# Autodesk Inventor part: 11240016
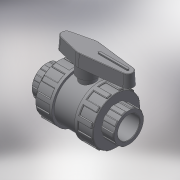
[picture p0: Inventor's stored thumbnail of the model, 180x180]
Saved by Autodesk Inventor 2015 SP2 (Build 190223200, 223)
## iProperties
Created: 2017-11
Part Number: 11240016
Material: Generic
Description: PLASSON BI STOP VALVE CEM PVC 16
Document SubType Name: Modeling
Designer: KIM
Density: 1 g/cm^3
Appearance: Default
Author: KIM
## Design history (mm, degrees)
derived "112400 - 112700.ipt"
feature "Solid1::112400 - 112700.ipt"
tag "TaggingFeature1"
body "Solid1"
other parameters: "d0" = 71, "d1" = 16, "d2" = 45, "d3" = 14, "d4" = 12.8, "d5" = 9.8, "d7" = 22.4, "d8" = 40.5, "d13" = 0.48, "d23" = 14, "d24" = 43.2, "d25" = 0.32, "d26" = 0.48, "d27" = 6.75, "d28" = 3.375, "d29" = 10.5, "d30" = 0, "d35" = 0.48, "d39" = 22.5, "d45" = 360 deg, "d47" = 0.32, "d50" = 24.75, "d51" = 13.5, "d53" = 0, "d55" = 3.2, "d56" = 1.6, "d57" = 9.8, "d58" = 0, "d59" = 0.48, "d61" = 360 deg, "d63" = 18, "d64" = 45, "d66" = 65, "d68" = 9, "d69" = 19.5, "d70" = 11.25, "d71" = 3 deg, "d73" = 0.9, "d74" = 26, "d75" = 1.35, "d76" = 0, "d77" = 0.32, "d_" = 16, "l_" = 14, "H_" = 71, "K_" = 45, "F_" = 45, "J_" = 65, "d67" = 18, "d72" = 4.5
